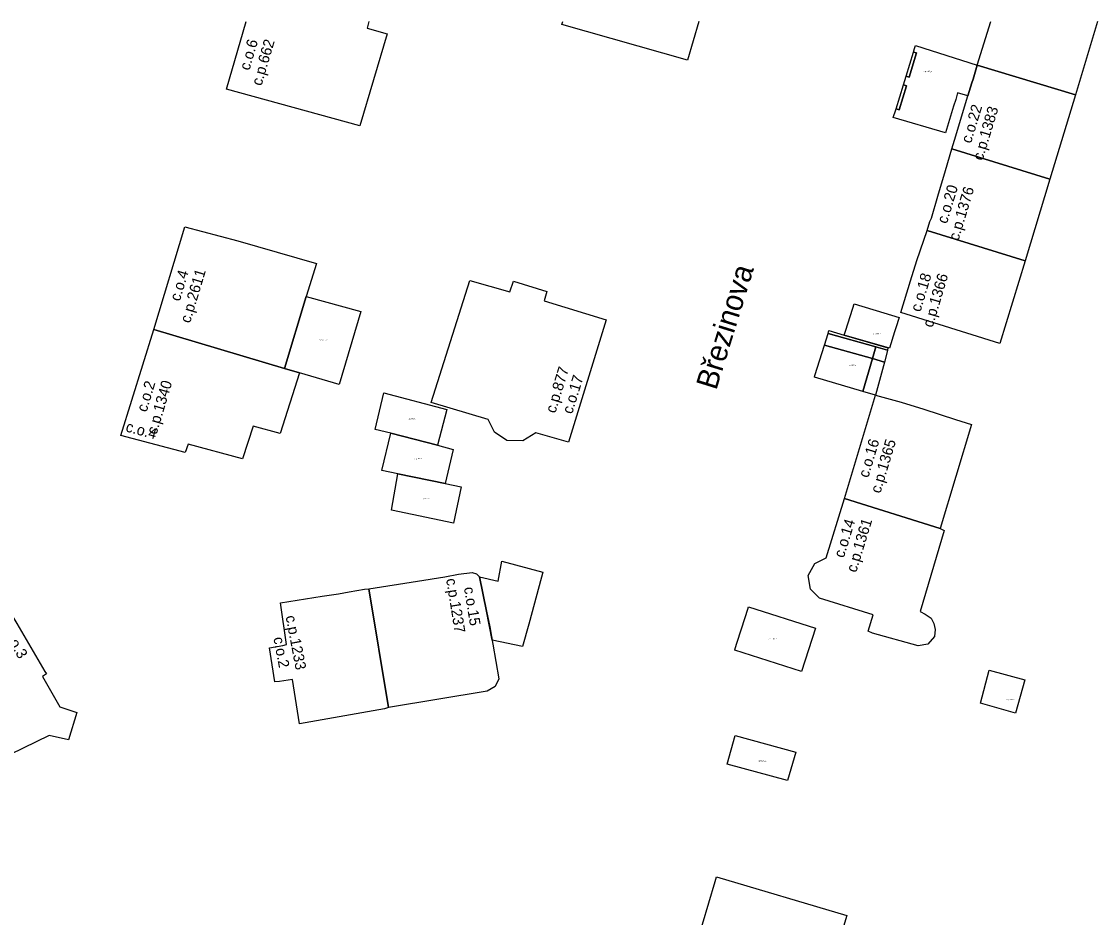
# Model space of a CAD drawing. Extents: x -600391 to -599491, y -1160176 to -1159402.
# Drawn here: x -600005.8 to -599905.8, y -1159485 to -1159401.8 of the extents above; entities that cross this region are included whole.
import ezdxf

# ---------------------------------------------------------------- set-up
doc = ezdxf.new("R2010")
doc.units = 0
for name, color, linetype in [('Level 10', 7, 'Continuous'), ('Level 11', 7, 'Continuous'), ('Level 12', 7, 'Continuous'), ('Level 25', 7, 'Continuous'), ('Level 61', 7, 'Continuous'), ('Level 62', 7, 'Continuous')]:
    doc.layers.add(name, color=color, linetype=linetype)

msp = doc.modelspace()

# ---------------------------------------------------------------- linework, layer by layer
at = {"layer": 'Level 61'}
for p, q in [((-599986.74, -1159408.06), (-599984.893, -1159401.769)), ((-599973.501, -1159401.769), (-599973.67, -1159402.38)), ((-599955.56, -1159402.05), (-599955.478, -1159401.769)), ((-599942.838, -1159401.769), (-599943.91, -1159405.37)), ((-599916.98, -1159405.83), (-599915.72, -1159401.769)), ((-599905.806, -1159401.769), (-599907.85, -1159408.58))]:
    msp.add_line(p, q, dxfattribs=at)
for points in [[(-599971.8, -1159402.92), (-599974.35, -1159411.47)], [(-599973.67, -1159402.38), (-599971.8, -1159402.92)], [(-599943.91, -1159405.37), (-599955.56, -1159402.05)], [(-599922.81, -1159404.29), (-599922.72, -1159403.99)], [(-599922.72, -1159403.99), (-599916.98, -1159405.83)], [(-599923.58, -1159406.85), (-599922.91, -1159404.61)], [(-599923.3, -1159406.93), (-599922.62, -1159404.69)], [(-599922.62, -1159404.69), (-599923.3, -1159406.93)], [(-599922.91, -1159404.61), (-599922.81, -1159404.29)], [(-599922.62, -1159404.69), (-599922.91, -1159404.61)], [(-599922.91, -1159404.61), (-599922.62, -1159404.69)], [(-599917.12, -1159406.26), (-599916.98, -1159405.83)], [(-599916.98, -1159405.83), (-599917.12, -1159406.26)], [(-599916.98, -1159405.83), (-599907.85, -1159408.58)], [(-599907.85, -1159408.58), (-599916.98, -1159405.83)], [(-599923.83, -1159407.66), (-599923.58, -1159406.85)], [(-599923.58, -1159406.85), (-599923.3, -1159406.93)], [(-599923.3, -1159406.93), (-599923.58, -1159406.85)], [(-599917.36, -1159407.12), (-599917.12, -1159406.26)], [(-599917.12, -1159406.26), (-599917.36, -1159407.12)], [(-599924.52, -1159409.89), (-599923.83, -1159407.66)], [(-599924.23, -1159409.98), (-599923.54, -1159407.75)], [(-599923.54, -1159407.75), (-599924.23, -1159409.98)], [(-599923.54, -1159407.75), (-599923.83, -1159407.66)], [(-599923.83, -1159407.66), (-599923.54, -1159407.75)], [(-599917.84, -1159408.68), (-599917.48, -1159407.47)], [(-599917.48, -1159407.47), (-599917.84, -1159408.68)], [(-599917.48, -1159407.47), (-599917.36, -1159407.12)], [(-599917.36, -1159407.12), (-599917.48, -1159407.47)], [(-599974.35, -1159411.47), (-599986.74, -1159408.06)], [(-599918.8, -1159408.4), (-599918.98, -1159409.01)], [(-599917.84, -1159408.68), (-599918.8, -1159408.4)], [(-599918.44, -1159410.63), (-599917.84, -1159408.68)], [(-599907.85, -1159408.58), (-599910.24, -1159416.4)], [(-599924.78, -1159410.68), (-599924.55, -1159409.98)], [(-599924.55, -1159409.98), (-599924.52, -1159409.89)], [(-599924.52, -1159409.89), (-599924.23, -1159409.98)], [(-599924.23, -1159409.98), (-599924.52, -1159409.89)], [(-599919.17, -1159409.63), (-599919.36, -1159410.25)], [(-599918.98, -1159409.01), (-599919.17, -1159409.63)], [(-599919.92, -1159412.11), (-599924.78, -1159410.68)], [(-599919.55, -1159410.87), (-599919.74, -1159411.49)], [(-599919.36, -1159410.25), (-599919.55, -1159410.87)], [(-599918.97, -1159412.39), (-599918.44, -1159410.63)], [(-599919.74, -1159411.49), (-599919.92, -1159412.11)], [(-599919.34, -1159413.6), (-599918.97, -1159412.39)], [(-599919.93, -1159415.62), (-599919.34, -1159413.6)], [(-599910.24, -1159416.4), (-599919.34, -1159413.6)], [(-599919.34, -1159413.6), (-599910.24, -1159416.4)], [(-599920.64, -1159417.99), (-599919.93, -1159415.62)], [(-599910.24, -1159416.4), (-599912.51, -1159424)], [(-599921.24, -1159420.02), (-599920.64, -1159417.99)], [(-599993.49, -1159430.39), (-599990.61, -1159420.85)], [(-599990.61, -1159420.85), (-599985.67, -1159422.15)], [(-599921.62, -1159421.19), (-599921.37, -1159420.35)], [(-599921.37, -1159420.35), (-599921.24, -1159420.02)], [(-599921.93, -1159422.08), (-599921.62, -1159421.19)], [(-599921.62, -1159421.19), (-599912.51, -1159424)], [(-599912.51, -1159424), (-599921.62, -1159421.19)], [(-599985.67, -1159422.15), (-599978.37, -1159424.23)], [(-599922.59, -1159423.97), (-599921.93, -1159422.08)], [(-599923.17, -1159425.84), (-599922.59, -1159423.97)], [(-599978.37, -1159424.23), (-599979.31, -1159427.32)], [(-599912.51, -1159424), (-599914.89, -1159431.67)], [(-599967.72, -1159437.15), (-599964.11, -1159425.81)], [(-599964.11, -1159425.81), (-599960.39, -1159426.89)], [(-599960.39, -1159426.89), (-599960.06, -1159425.88)], [(-599960.06, -1159425.88), (-599956.98, -1159426.84)], [(-599924.09, -1159428.79), (-599923.17, -1159425.84)], [(-599956.98, -1159426.84), (-599957.21, -1159427.7)], [(-599981.35, -1159434), (-599979.31, -1159427.32)], [(-599979.31, -1159427.32), (-599981.35, -1159434)], [(-599979.31, -1159427.32), (-599974.26, -1159428.69)], [(-599957.21, -1159427.7), (-599951.46, -1159429.47)], [(-599928.53, -1159428.4), (-599928.4, -1159427.99)], [(-599928.4, -1159427.99), (-599925.64, -1159428.82)], [(-599974.26, -1159428.69), (-599976.27, -1159435.47)], [(-599929.23, -1159430.54), (-599928.53, -1159428.4)], [(-599925.64, -1159428.82), (-599924.23, -1159429.25)], [(-599914.89, -1159431.67), (-599924.09, -1159428.79)], [(-599951.46, -1159429.47), (-599954.96, -1159440.83)], [(-599924.23, -1159429.25), (-599924.54, -1159430.23)], [(-599996.55, -1159440.22), (-599993.49, -1159430.39)], [(-599993.49, -1159430.39), (-599981.35, -1159434)], [(-599981.35, -1159434), (-599993.49, -1159430.39)], [(-599931.18, -1159431.84), (-599930.84, -1159430.75)], [(-599930.84, -1159430.75), (-599930.75, -1159430.48)], [(-599930.84, -1159430.75), (-599926.4, -1159432)], [(-599926.4, -1159432), (-599930.84, -1159430.75)], [(-599930.75, -1159430.48), (-599929.34, -1159430.89)], [(-599929.34, -1159430.89), (-599929.23, -1159430.54)], [(-599925.12, -1159432.11), (-599929.34, -1159430.89)], [(-599929.34, -1159430.89), (-599925.27, -1159432.07)], [(-599924.65, -1159430.59), (-599925.12, -1159432.11)], [(-599924.54, -1159430.23), (-599924.65, -1159430.59)], [(-599932.07, -1159434.65), (-599931.18, -1159431.84)], [(-599926.71, -1159433.08), (-599931.18, -1159431.84)], [(-599931.18, -1159431.84), (-599926.71, -1159433.08)], [(-599926.71, -1159433.08), (-599926.4, -1159432)], [(-599926.4, -1159432), (-599926.71, -1159433.08)], [(-599926.4, -1159432), (-599925.32, -1159432.3)], [(-599925.32, -1159432.3), (-599926.4, -1159432)], [(-599925.32, -1159432.3), (-599925.55, -1159433.32)], [(-599925.27, -1159432.07), (-599925.32, -1159432.3)], [(-599927.61, -1159436.12), (-599926.71, -1159433.08)], [(-599926.71, -1159433.08), (-599927.61, -1159436.12)], [(-599926.71, -1159433.08), (-599925.58, -1159433.42)], [(-599925.58, -1159433.42), (-599926.71, -1159433.08)], [(-599925.58, -1159433.42), (-599926.42, -1159436.47)], [(-599925.55, -1159433.32), (-599925.58, -1159433.42)], [(-599979.93, -1159434.39), (-599981.74, -1159440.05)], [(-599981.35, -1159434), (-599979.93, -1159434.39)], [(-599979.93, -1159434.39), (-599981.35, -1159434)], [(-599976.27, -1159435.47), (-599979.93, -1159434.39)], [(-599932.11, -1159434.8), (-599932.07, -1159434.65)], [(-599927.61, -1159436.12), (-599932.11, -1159434.8)], [(-599972.91, -1159439.66), (-599972.1, -1159436.26)], [(-599972.1, -1159436.26), (-599966.26, -1159437.8)], [(-599929.31, -1159446.08), (-599926.42, -1159436.47)], [(-599926.42, -1159436.47), (-599927.61, -1159436.12)], [(-599926.42, -1159436.47), (-599924.04, -1159437.14)], [(-599962.41, -1159438.72), (-599967.72, -1159437.15)], [(-599966.26, -1159437.8), (-599967.11, -1159441.12)], [(-599924.04, -1159437.14), (-599921.94, -1159437.76)], [(-599921.94, -1159437.76), (-599918.99, -1159438.72)], [(-599961.84, -1159439.91), (-599962.41, -1159438.72)], [(-599918.99, -1159438.72), (-599917.5, -1159439.21)], [(-599984.25, -1159439.36), (-599985.23, -1159442.39)], [(-599981.74, -1159440.05), (-599984.25, -1159439.36)], [(-599971.45, -1159440), (-599972.91, -1159439.66)], [(-599960.68, -1159440.68), (-599961.84, -1159439.91)], [(-599958, -1159439.98), (-599959.2, -1159440.72)], [(-599954.96, -1159440.83), (-599958, -1159439.98)], [(-599917.5, -1159439.21), (-599920.43, -1159448.86)], [(-599990.56, -1159441.81), (-599996.55, -1159440.22)], [(-599972.28, -1159443.48), (-599971.45, -1159440)], [(-599971.45, -1159440), (-599967.11, -1159441.12)], [(-599967.11, -1159441.12), (-599971.45, -1159440)], [(-599959.2, -1159440.72), (-599960.68, -1159440.68)], [(-599990.28, -1159441.02), (-599990.56, -1159441.81)], [(-599985.23, -1159442.39), (-599990.28, -1159441.02)], [(-599967.11, -1159441.12), (-599965.67, -1159441.52)], [(-599965.67, -1159441.52), (-599966.42, -1159444.68)], [(-599970.82, -1159443.78), (-599972.28, -1159443.48)], [(-599971.41, -1159447.16), (-599970.82, -1159443.78)], [(-599966.42, -1159444.68), (-599970.82, -1159443.78)], [(-599970.82, -1159443.78), (-599966.42, -1159444.68)], [(-599966.42, -1159444.68), (-599964.93, -1159444.99)], [(-599964.93, -1159444.99), (-599965.65, -1159448.35)], [(-599931, -1159451.57), (-599929.31, -1159446.08)], [(-599929.31, -1159446.08), (-599920.43, -1159448.86)], [(-599920.43, -1159448.86), (-599929.31, -1159446.08)], [(-599965.65, -1159448.35), (-599971.41, -1159447.16)], [(-599920.43, -1159448.86), (-599920.06, -1159449.03)], [(-599920.06, -1159449.03), (-599922.29, -1159456.57)], [(-599961.5, -1159453.74), (-599961.16, -1159451.89)], [(-599961.16, -1159451.89), (-599957.34, -1159452.93)], [(-599932.08, -1159452.1), (-599931, -1159451.57)], [(-599965.18, -1159453.11), (-599963.9, -1159452.96)], [(-599963.9, -1159452.96), (-599963.51, -1159453.07)], [(-599957.34, -1159452.93), (-599958.34, -1159456.61)], [(-599932.68, -1159453.22), (-599932.08, -1159452.1)], [(-599973.49, -1159454.45), (-599968.99, -1159453.75)], [(-599968.99, -1159453.75), (-599966.44, -1159453.34)], [(-599966.44, -1159453.34), (-599965.18, -1159453.11)], [(-599963.51, -1159453.07), (-599963.23, -1159453.34)], [(-599962.57, -1159456.54), (-599963.23, -1159453.34)], [(-599963.23, -1159453.34), (-599961.5, -1159453.74)], [(-599963.23, -1159453.34), (-599962.57, -1159456.54)], [(-599932.48, -1159454.48), (-599932.68, -1159453.22)], [(-599977.84, -1159455.16), (-599976.33, -1159454.93)], [(-599976.33, -1159454.93), (-599975.33, -1159454.75)], [(-599975.33, -1159454.75), (-599973.89, -1159454.49)], [(-599973.89, -1159454.49), (-599973.49, -1159454.45)], [(-599971.66, -1159465.49), (-599973.49, -1159454.45)], [(-599973.49, -1159454.45), (-599971.66, -1159465.49)], [(-599931.63, -1159455.33), (-599932.48, -1159454.48)], [(-599981.7, -1159455.76), (-599977.84, -1159455.16)], [(-599981.14, -1159459.63), (-599981.7, -1159455.76)], [(-599926.66, -1159456.89), (-599931.63, -1159455.33)], [(-599962.05, -1159459.23), (-599962.57, -1159456.54)], [(-599962.57, -1159456.54), (-599962.27, -1159457.99)], [(-599958.34, -1159456.61), (-599958.65, -1159457.76)], [(-599938.55, -1159457.14), (-599938.29, -1159456.34)], [(-599938.29, -1159456.34), (-599938.23, -1159456.14)], [(-599938.23, -1159456.14), (-599932.01, -1159458.12)], [(-599927.12, -1159458.4), (-599926.66, -1159456.89)], [(-599922.29, -1159456.57), (-599921.81, -1159456.81)], [(-599921.81, -1159456.81), (-599921.26, -1159457.2)], [(-600006.21, -1159457.68), (-600003.6, -1159462.13)], [(-599958.65, -1159457.76), (-599959.21, -1159459.83)], [(-599939.27, -1159459.41), (-599938.55, -1159457.14)], [(-599921.26, -1159457.2), (-599921, -1159457.68)], [(-599921, -1159457.68), (-599920.89, -1159458.25)], [(-599962.27, -1159457.99), (-599961.42, -1159462.82)], [(-599932.01, -1159458.12), (-599933.29, -1159462.15)], [(-599926.7, -1159458.57), (-599927.12, -1159458.4)], [(-599922.47, -1159459.77), (-599926.7, -1159458.57)], [(-599920.95, -1159458.88), (-599921.58, -1159459.6)], [(-599920.89, -1159458.25), (-599920.95, -1159458.88)], [(-599982.73, -1159459.94), (-599981.49, -1159459.72)], [(-599982.22, -1159463.09), (-599982.73, -1159459.94)], [(-599981.49, -1159459.72), (-599981.14, -1159459.63)], [(-599959.21, -1159459.83), (-599962.05, -1159459.23)], [(-599939.46, -1159460.02), (-599939.27, -1159459.41)], [(-599921.58, -1159459.6), (-599922.47, -1159459.77)], [(-599939.51, -1159460.17), (-599939.46, -1159460.02)], [(-599933.29, -1159462.15), (-599939.51, -1159460.17)], [(-600003.46, -1159462.37), (-600003.82, -1159462.61)], [(-600003.82, -1159462.61), (-600002.22, -1159465.43)], [(-600003.6, -1159462.13), (-600003.46, -1159462.37)], [(-599980.6, -1159462.89), (-599981.8, -1159463.06)], [(-599979.95, -1159467), (-599980.6, -1159462.89)], [(-599961.42, -1159462.82), (-599961.76, -1159463.52)], [(-599916.67, -1159465.07), (-599915.88, -1159462.02)], [(-599915.88, -1159462.02), (-599912.55, -1159462.93)], [(-599912.55, -1159462.93), (-599913.41, -1159466.02)], [(-599981.8, -1159463.06), (-599982.22, -1159463.09)], [(-599962.5, -1159463.98), (-599971.66, -1159465.49)], [(-599961.76, -1159463.52), (-599962.5, -1159463.98)], [(-600002.22, -1159465.43), (-600000.63, -1159465.94)], [(-600000.63, -1159465.94), (-600001.39, -1159468.49)], [(-599972.06, -1159465.6), (-599979.95, -1159467)], [(-599971.95, -1159465.57), (-599972.06, -1159465.6)], [(-599971.66, -1159465.49), (-599971.95, -1159465.57)], [(-599913.41, -1159466.02), (-599916.67, -1159465.07)], [(-600003.19, -1159468.1), (-600010.53, -1159471.65)], [(-600001.39, -1159468.49), (-600003.19, -1159468.1)], [(-599940.2, -1159470.74), (-599939.47, -1159468.08)], [(-599939.47, -1159468.08), (-599933.82, -1159469.63)], [(-599933.82, -1159469.63), (-599934.6, -1159472.28)], [(-599934.6, -1159472.28), (-599940.2, -1159470.74)], [(-599942.5, -1159485.62), (-599941.33, -1159481.65)], [(-599941.33, -1159481.65), (-599941.19, -1159481.21)], [(-599941.19, -1159481.21), (-599929.09, -1159484.81)], [(-599929.09, -1159484.81), (-599934.87, -1159504.09)]]:
    msp.add_lwpolyline(points, dxfattribs=at)
at = {"layer": 'Level 62'}
msp.add_line((-599916.98, -1159405.83), (-599915.72, -1159401.769), dxfattribs=at)
for points in [[(-599973.501, -1159401.769), (-599973.67, -1159402.38), (-599971.8, -1159402.92), (-599974.35, -1159411.47), (-599986.74, -1159408.06), (-599984.893, -1159401.769)], [(-599942.838, -1159401.769), (-599943.91, -1159405.37), (-599955.56, -1159402.05), (-599955.478, -1159401.769)], [(-599905.806, -1159401.769), (-599907.85, -1159408.58), (-599916.98, -1159405.83)], [(-599919.92, -1159412.11), (-599924.78, -1159410.68), (-599924.55, -1159409.98), (-599924.52, -1159409.89), (-599924.23, -1159409.98), (-599923.54, -1159407.75), (-599923.83, -1159407.66), (-599923.58, -1159406.85), (-599923.3, -1159406.93), (-599922.62, -1159404.69), (-599922.91, -1159404.61), (-599922.81, -1159404.29), (-599922.72, -1159403.99), (-599916.98, -1159405.83), (-599917.12, -1159406.26), (-599917.36, -1159407.12), (-599917.48, -1159407.47), (-599917.84, -1159408.68), (-599918.8, -1159408.4), (-599918.98, -1159409.01), (-599919.17, -1159409.63), (-599919.36, -1159410.25), (-599919.55, -1159410.87), (-599919.74, -1159411.49), (-599919.92, -1159412.11)], [(-599922.91, -1159404.61), (-599922.62, -1159404.69), (-599923.3, -1159406.93), (-599923.58, -1159406.85), (-599922.91, -1159404.61)], [(-599916.98, -1159405.83), (-599907.85, -1159408.58), (-599910.24, -1159416.4), (-599919.34, -1159413.6), (-599918.97, -1159412.39), (-599918.44, -1159410.63), (-599917.84, -1159408.68), (-599917.48, -1159407.47), (-599917.36, -1159407.12), (-599917.12, -1159406.26), (-599916.98, -1159405.83)], [(-599923.83, -1159407.66), (-599923.54, -1159407.75), (-599924.23, -1159409.98), (-599924.52, -1159409.89), (-599923.83, -1159407.66)], [(-599912.51, -1159424), (-599921.62, -1159421.19), (-599921.37, -1159420.35), (-599921.24, -1159420.02), (-599920.64, -1159417.99), (-599919.93, -1159415.62), (-599919.34, -1159413.6), (-599910.24, -1159416.4), (-599912.51, -1159424)], [(-599978.37, -1159424.23), (-599979.31, -1159427.32), (-599981.35, -1159434), (-599993.49, -1159430.39), (-599990.61, -1159420.85), (-599985.67, -1159422.15), (-599978.37, -1159424.23)], [(-599912.51, -1159424), (-599914.89, -1159431.67), (-599924.09, -1159428.79), (-599923.17, -1159425.84), (-599922.59, -1159423.97), (-599921.93, -1159422.08), (-599921.62, -1159421.19), (-599912.51, -1159424)], [(-599951.46, -1159429.47), (-599954.96, -1159440.83), (-599958, -1159439.98), (-599959.2, -1159440.72), (-599960.68, -1159440.68), (-599961.84, -1159439.91), (-599962.41, -1159438.72), (-599967.72, -1159437.15), (-599964.11, -1159425.81), (-599960.39, -1159426.89), (-599960.06, -1159425.88), (-599956.98, -1159426.84), (-599957.21, -1159427.7), (-599951.46, -1159429.47)], [(-599979.31, -1159427.32), (-599974.26, -1159428.69), (-599976.27, -1159435.47), (-599979.93, -1159434.39), (-599981.35, -1159434), (-599979.31, -1159427.32)], [(-599924.23, -1159429.25), (-599924.54, -1159430.23), (-599924.65, -1159430.59), (-599925.12, -1159432.11), (-599929.34, -1159430.89), (-599929.23, -1159430.54), (-599928.53, -1159428.4), (-599928.4, -1159427.99), (-599925.64, -1159428.82), (-599924.23, -1159429.25)], [(-599993.49, -1159430.39), (-599981.35, -1159434), (-599979.93, -1159434.39), (-599981.74, -1159440.05), (-599984.25, -1159439.36), (-599985.23, -1159442.39), (-599990.28, -1159441.02), (-599990.56, -1159441.81), (-599996.55, -1159440.22), (-599993.49, -1159430.39)], [(-599926.71, -1159433.08), (-599931.18, -1159431.84), (-599930.84, -1159430.75), (-599926.4, -1159432), (-599926.71, -1159433.08)], [(-599926.4, -1159432), (-599930.84, -1159430.75), (-599930.75, -1159430.48), (-599929.34, -1159430.89), (-599925.27, -1159432.07), (-599925.32, -1159432.3), (-599926.4, -1159432)], [(-599926.71, -1159433.08), (-599927.61, -1159436.12), (-599932.11, -1159434.8), (-599932.07, -1159434.65), (-599931.18, -1159431.84), (-599926.71, -1159433.08)], [(-599926.71, -1159433.08), (-599926.4, -1159432), (-599925.32, -1159432.3), (-599925.55, -1159433.32), (-599925.58, -1159433.42), (-599926.71, -1159433.08)], [(-599926.71, -1159433.08), (-599925.58, -1159433.42), (-599926.42, -1159436.47), (-599927.61, -1159436.12), (-599926.71, -1159433.08)], [(-599971.45, -1159440), (-599972.91, -1159439.66), (-599972.1, -1159436.26), (-599966.26, -1159437.8), (-599967.11, -1159441.12), (-599971.45, -1159440)], [(-599929.31, -1159446.08), (-599926.42, -1159436.47), (-599924.04, -1159437.14), (-599921.94, -1159437.76), (-599918.99, -1159438.72), (-599917.5, -1159439.21), (-599920.43, -1159448.86), (-599929.31, -1159446.08)], [(-599970.82, -1159443.78), (-599972.28, -1159443.48), (-599971.45, -1159440), (-599967.11, -1159441.12), (-599965.67, -1159441.52), (-599966.42, -1159444.68), (-599970.82, -1159443.78)], [(-599970.82, -1159443.78), (-599966.42, -1159444.68), (-599964.93, -1159444.99), (-599965.65, -1159448.35), (-599971.41, -1159447.16), (-599970.82, -1159443.78)], [(-599929.31, -1159446.08), (-599920.43, -1159448.86), (-599920.06, -1159449.03), (-599922.29, -1159456.57), (-599921.81, -1159456.81), (-599921.26, -1159457.2), (-599921, -1159457.68), (-599920.89, -1159458.25), (-599920.95, -1159458.88), (-599921.58, -1159459.6), (-599922.47, -1159459.77), (-599926.7, -1159458.57), (-599927.12, -1159458.4), (-599926.66, -1159456.89), (-599931.63, -1159455.33), (-599932.48, -1159454.48), (-599932.68, -1159453.22), (-599932.08, -1159452.1), (-599931, -1159451.57), (-599929.31, -1159446.08)], [(-599962.05, -1159459.23), (-599962.57, -1159456.54), (-599963.23, -1159453.34), (-599961.5, -1159453.74), (-599961.16, -1159451.89), (-599957.34, -1159452.93), (-599958.34, -1159456.61), (-599958.65, -1159457.76), (-599959.21, -1159459.83), (-599962.05, -1159459.23)], [(-599966.44, -1159453.34), (-599965.18, -1159453.11), (-599963.9, -1159452.96), (-599963.51, -1159453.07), (-599963.23, -1159453.34), (-599962.57, -1159456.54), (-599962.27, -1159457.99), (-599961.42, -1159462.82), (-599961.76, -1159463.52), (-599962.5, -1159463.98), (-599971.66, -1159465.49), (-599973.49, -1159454.45), (-599968.99, -1159453.75), (-599966.44, -1159453.34)], [(-599981.8, -1159463.06), (-599982.22, -1159463.09), (-599982.73, -1159459.94), (-599981.49, -1159459.72), (-599981.14, -1159459.63), (-599981.7, -1159455.76), (-599977.84, -1159455.16), (-599976.33, -1159454.93), (-599975.33, -1159454.75), (-599973.89, -1159454.49), (-599973.49, -1159454.45), (-599971.66, -1159465.49), (-599971.95, -1159465.57), (-599972.06, -1159465.6), (-599979.95, -1159467), (-599980.6, -1159462.89), (-599981.8, -1159463.06)], [(-600015.87, -1159469.86), (-600016.35, -1159470.15), (-600018.81, -1159465.7), (-600016.63, -1159464.47), (-600015.37, -1159462.68), (-600016.04, -1159461.43), (-600014.76, -1159460.73), (-600015.18, -1159460.01), (-600011.66, -1159458.03), (-600011.34, -1159457.83), (-600010.75, -1159458.82), (-600006.79, -1159456.69), (-600006.21, -1159457.68), (-600003.6, -1159462.13), (-600003.46, -1159462.37), (-600003.82, -1159462.61), (-600002.22, -1159465.43), (-600000.63, -1159465.94), (-600001.39, -1159468.49), (-600003.19, -1159468.1), (-600010.53, -1159471.65), (-600011.32, -1159470.22), (-600012.53, -1159467.97), (-600015.87, -1159469.86)], [(-599938.29, -1159456.34), (-599938.23, -1159456.14), (-599932.01, -1159458.12), (-599933.29, -1159462.15), (-599939.51, -1159460.17), (-599939.46, -1159460.02), (-599939.27, -1159459.41), (-599938.55, -1159457.14), (-599938.29, -1159456.34)], [(-599916.67, -1159465.07), (-599915.88, -1159462.02), (-599912.55, -1159462.93), (-599913.41, -1159466.02), (-599916.67, -1159465.07)], [(-599940.2, -1159470.74), (-599939.47, -1159468.08), (-599933.82, -1159469.63), (-599934.6, -1159472.28), (-599940.2, -1159470.74)], [(-599946.86, -1159500.37), (-599942.5, -1159485.62), (-599941.33, -1159481.65), (-599941.19, -1159481.21), (-599929.09, -1159484.81), (-599934.87, -1159504.09), (-599946.86, -1159500.37)]]:
    msp.add_lwpolyline(points, dxfattribs=at)

# ---------------------------------------------------------------- texts
at = {"layer": 'Level 10'}
for s, rotation, p in [('c.o.6', 73.63827, (-599984.605, -1159406.369)), ('c.o.22', 73.10538, (-599917.56, -1159413.143)), ('c.o.20', 73.27935, (-599919.798, -1159420.61)), ('c.o.4', 73.21953, (-599991.067, -1159427.813)), ('c.o.18', 73.30295, (-599922.261, -1159428.804)), ('c.o.17', 72.87874, (-599954.616, -1159438.285)), ('c.o.2', 73.31557, (-599994.154, -1159438.104)), ('c.o.4', 344.75192, (-599996.156, -1159439.827)), ('c.o.16', 73.26124, (-599927.104, -1159444.207)), ('c.o.14', 72.92044, (-599929.377, -1159451.652)), ('c.o.15', 279.19574, (-599964.673, -1159454.358)), ('c.o.3', 300.51174, (-600007.471, -1159458.553)), ('c.o.2', 280.79529, (-599982.378, -1159459.024))]:
    msp.add_text(s, height=1, rotation=rotation, dxfattribs=at).set_placement(p)
at = {"layer": 'Level 11'}
msp.add_text('Březinova', height=2, rotation=72.82466, dxfattribs=at).set_placement((-599941.227, -1159436.081))
at = {"layer": 'Level 12'}
for s, rotation, p in [('c.p.662', 73.63827, (-599983.474, -1159407.8)), ('c.p.1383', 73.10538, (-599916.486, -1159414.741)), ('c.p.1376', 73.27935, (-599918.724, -1159422.195)), ('c.p.2611', 73.21953, (-599990.116, -1159429.843)), ('c.p.1366', 73.30295, (-599921.135, -1159430.258)), ('c.p.877', 72.87874, (-599956.179, -1159438.212)), ('c.p.1340', 73.31557, (-599993.23, -1159440.199)), ('c.p.1365', 73.26124, (-599925.985, -1159445.655)), ('c.p.1361', 72.92044, (-599928.228, -1159453.006)), ('c.p.1237', 279.19574, (-599966.33, -1159453.566)), ('c.p.1233', 280.79529, (-599981.241, -1159457.024))]:
    msp.add_text(s, height=1, rotation=rotation, dxfattribs=at).set_placement(p)
at = {"layer": 'Level 25'}
for s, p in [('c.pp.1383_A', (-599921.948, -1159406.447)), ('c.pp.1366_A', (-599926.708, -1159430.837)), ('c.pp.2611_A', (-599978.123, -1159431.377)), ('c.pp.1365_A', (-599929.002, -1159433.749)), ('c.pp.877_A', (-599969.883, -1159438.707)), ('c.pp.877_B', (-599969.243, -1159442.447)), ('c.pp.877_C', (-599968.579, -1159446.127)), ('c.pp.1361_A', (-599936.378, -1159459.167)), ('c.pp.1361_C', (-599914.304, -1159464.797)), ('c.pp.1361_B', (-599937.328, -1159470.477))]:
    msp.add_text(s, height=0.1, dxfattribs=at).set_placement(p)

doc.saveas('drawing.dxf')
